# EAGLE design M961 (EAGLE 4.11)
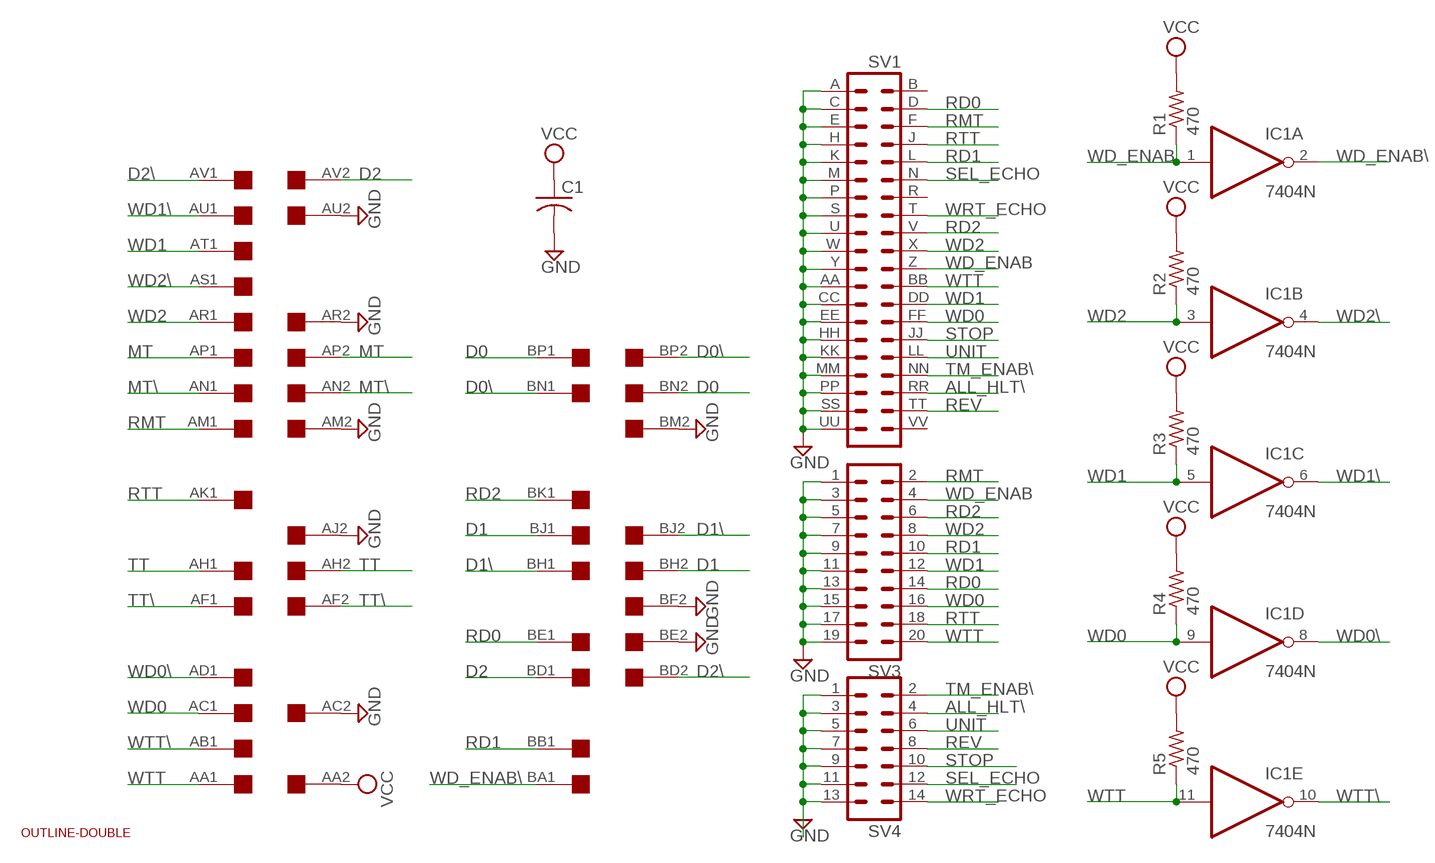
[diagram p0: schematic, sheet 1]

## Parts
C1  C-US050-025X075  [C050-025X075]
EDGE$1  DOUBLE  [EDGE-CON4]
IC1  7404N  [DIL14]
R1  470  R-US_0207/10  [0207/10]
R2  470  R-US_0207/10  [0207/10]
R3  470  R-US_0207/10  [0207/10]
R4  470  R-US_0207/10  [0207/10]
R5  470  R-US_0207/10  [0207/10]
SV1  DEC40PIN  [DEC40PIN]
SV3  MA10-2  [MA10-2]
SV4  MA07-2  [MA07-2]
U$2  OUTLINE-DOUBLE  [DOUBLE]

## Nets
ALL_HLT\: SV1.RR SV4.4
D0: EDGE$1.BN2 EDGE$1.BP1
D0\: EDGE$1.BN1 EDGE$1.BP2
D1: EDGE$1.BH2 EDGE$1.BJ1
D1\: EDGE$1.BH1 EDGE$1.BJ2
D2: EDGE$1.AV2 EDGE$1.BD1
D2\: EDGE$1.AV1 EDGE$1.BD2
GND: C1.2 EDGE$1.AC2 EDGE$1.AJ2 EDGE$1.AM2 EDGE$1.AR2 EDGE$1.AU2 EDGE$1.BE2 EDGE$1.BF2 EDGE$1.BM2 SV1.A SV1.AA SV1.C SV1.CC SV1.E SV1.EE SV1.H SV1.HH SV1.K SV1.KK SV1.M SV1.MM SV1.P SV1.PP SV1.S SV1.SS SV1.U SV1.UU SV1.W SV1.Y SV3.1 SV3.3 SV3.5 SV3.7 SV3.9 SV3.11 SV3.13 SV3.15 SV3.17 SV3.19 SV4.1 SV4.3 SV4.5 SV4.7 SV4.9 SV4.11 SV4.13
MT: EDGE$1.AP1 EDGE$1.AP2
MT\: EDGE$1.AN1 EDGE$1.AN2
RD0: EDGE$1.BE1 SV1.D SV3.14
RD1: EDGE$1.BB1 SV1.L SV3.10
RD2: EDGE$1.BK1 SV1.V SV3.6
REV: SV1.TT SV4.8
RMT: EDGE$1.AM1 SV1.F SV3.2
RTT: EDGE$1.AK1 SV1.J SV3.18
SEL_ECHO: SV1.N SV4.12
STOP: SV1.JJ SV4.10
TM_ENAB\: SV1.NN SV4.2
TT: EDGE$1.AH1 EDGE$1.AH2
TT\: EDGE$1.AF1 EDGE$1.AF2
UNIT: SV1.LL SV4.6
VCC: C1.1 EDGE$1.AA2 R1.2 R2.2 R3.2 R4.2 R5.2
WD0: EDGE$1.AC1 IC1.9(D:I) R4.1 SV1.FF SV3.16
WD0\: EDGE$1.AD1 IC1.8(D:O)
WD1: EDGE$1.AT1 IC1.5(C:I) R3.1 SV1.DD SV3.12
WD1\: EDGE$1.AU1 IC1.6(C:O)
WD2: EDGE$1.AR1 IC1.3(B:I) R2.1 SV1.X SV3.8
WD2\: EDGE$1.AS1 IC1.4(B:O)
WD_ENAB: IC1.1(A:I) R1.1 SV1.Z SV3.4
WD_ENAB\: EDGE$1.BA1 IC1.2(A:O)
WRT_ECHO: SV1.T SV4.14
WTT: EDGE$1.AA1 IC1.11(E:I) R5.1 SV1.BB SV3.20
WTT\: EDGE$1.AB1 IC1.10(E:O)
Unconnected: EDGE$1.AB2 EDGE$1.AD2 EDGE$1.AE1 EDGE$1.AE2 EDGE$1.AJ1 EDGE$1.AK2 EDGE$1.AL1 EDGE$1.AL2 EDGE$1.AS2 EDGE$1.AT2 EDGE$1.BA2 EDGE$1.BB2 EDGE$1.BC1 EDGE$1.BC2 EDGE$1.BF1 EDGE$1.BK2 EDGE$1.BL1 EDGE$1.BL2 EDGE$1.BM1 EDGE$1.BR1 EDGE$1.BR2 EDGE$1.BS1 EDGE$1.BS2 EDGE$1.BT1 EDGE$1.BT2 EDGE$1.BU1 EDGE$1.BU2 EDGE$1.BV1 EDGE$1.BV2 IC1.12(F:O) IC1.13(F:I) SV1.B SV1.R SV1.VV

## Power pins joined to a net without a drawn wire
GND: IC1.7(P:GND)
VCC: IC1.14(P:VCC)

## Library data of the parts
C1 = rcl:C-US: CAPACITOR, American symbol
EDGE$1 = dec-con:DOUBLE: Double-Height DEC board
IC1 = 74xx-us:74*04: Hex INVERTER
R1-R5 = rcl:R-US_: RESISTOR, American symbol
SV1 = dec-con:DEC40PIN: PIN HEADER
SV3 = con-lstb:MA10-2: PIN HEADER
SV4 = con-lstb:MA07-2: PIN HEADER
U$2 = dec-con:OUTLINE-*: Board outlines for DEC boards.

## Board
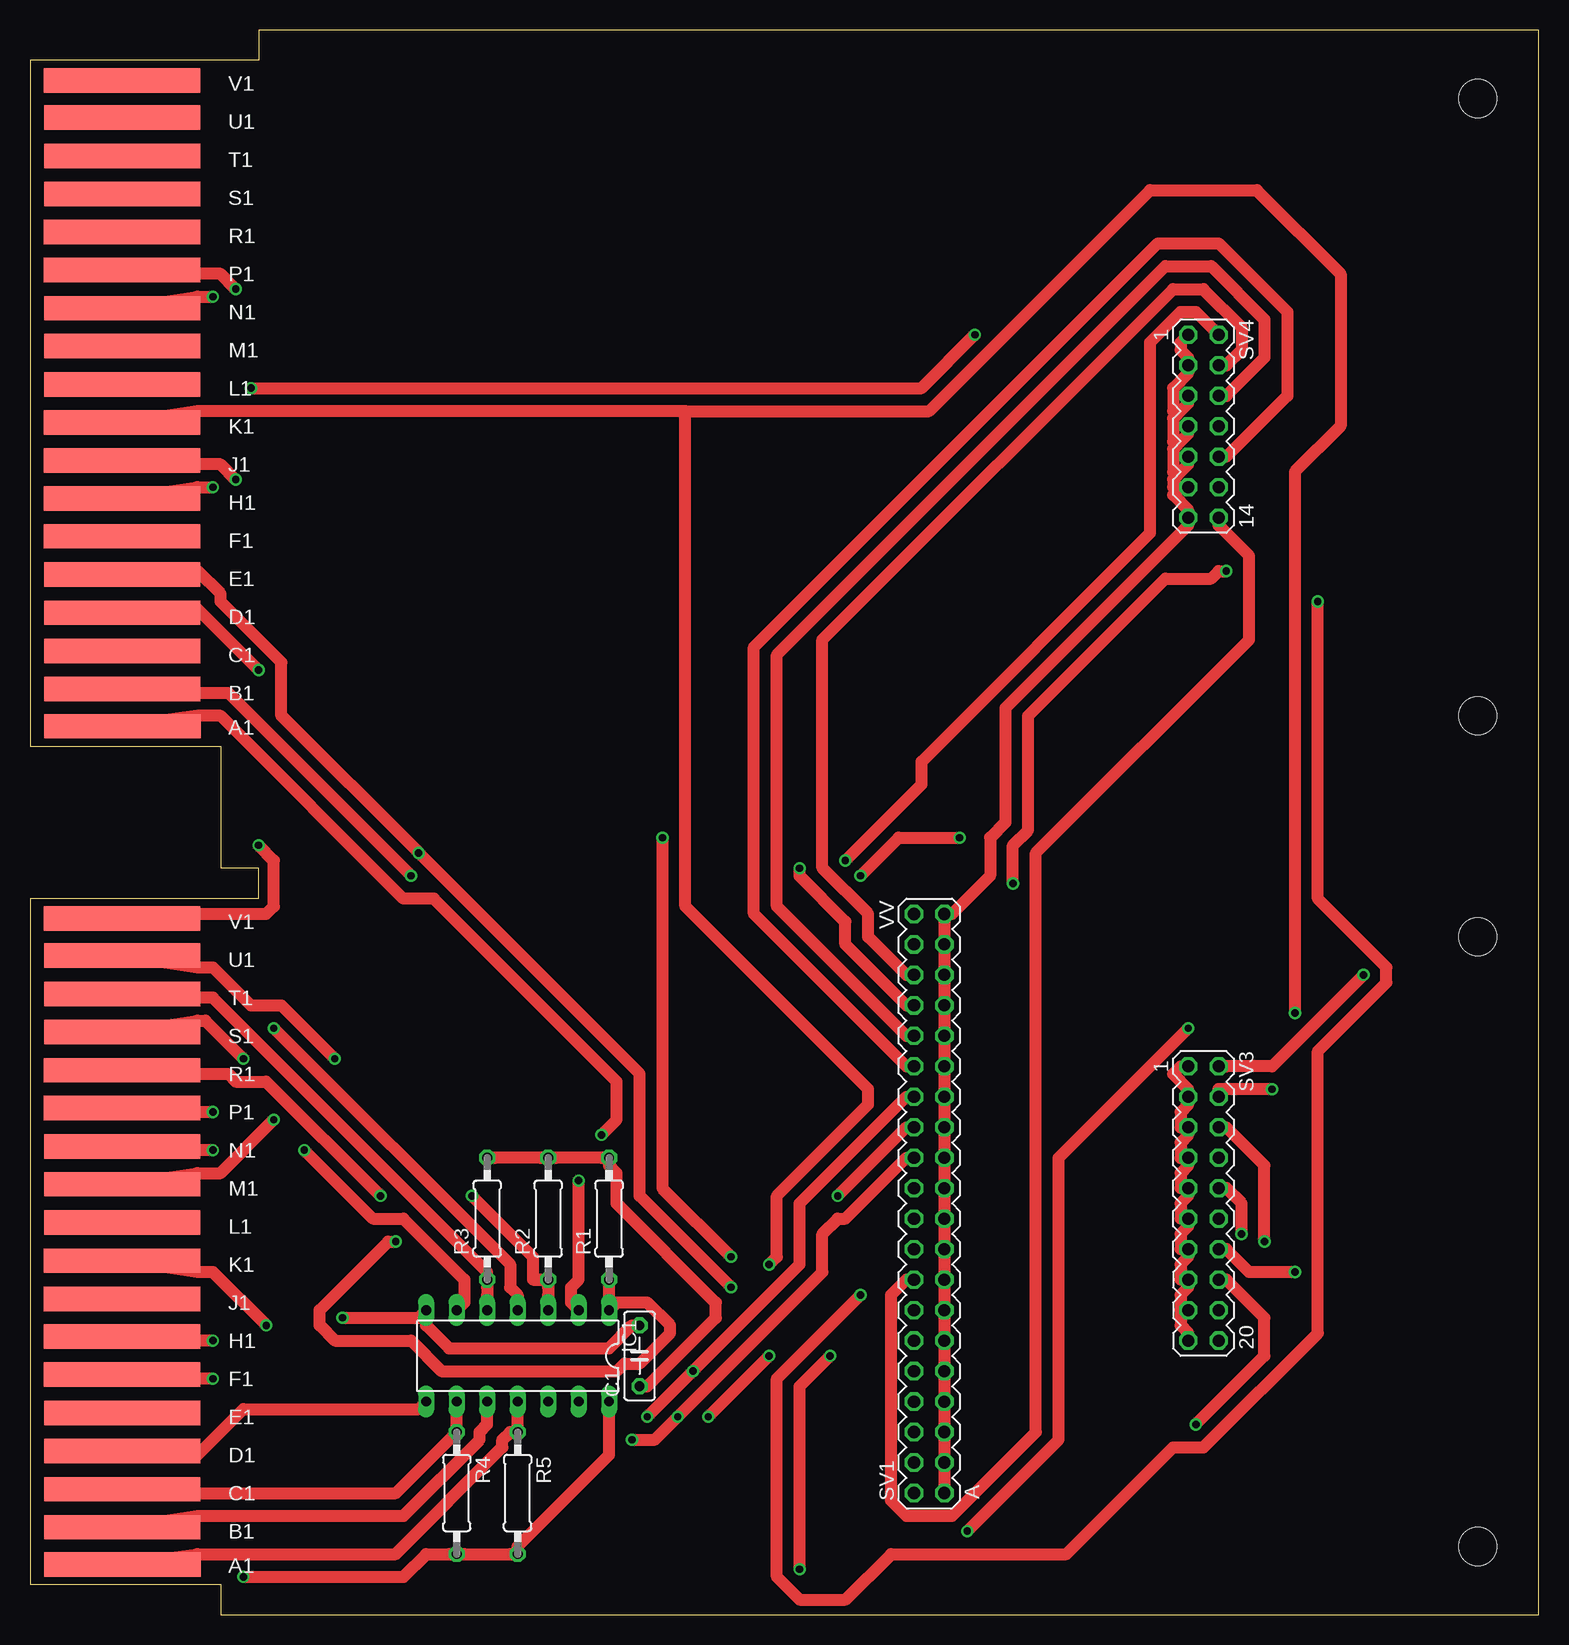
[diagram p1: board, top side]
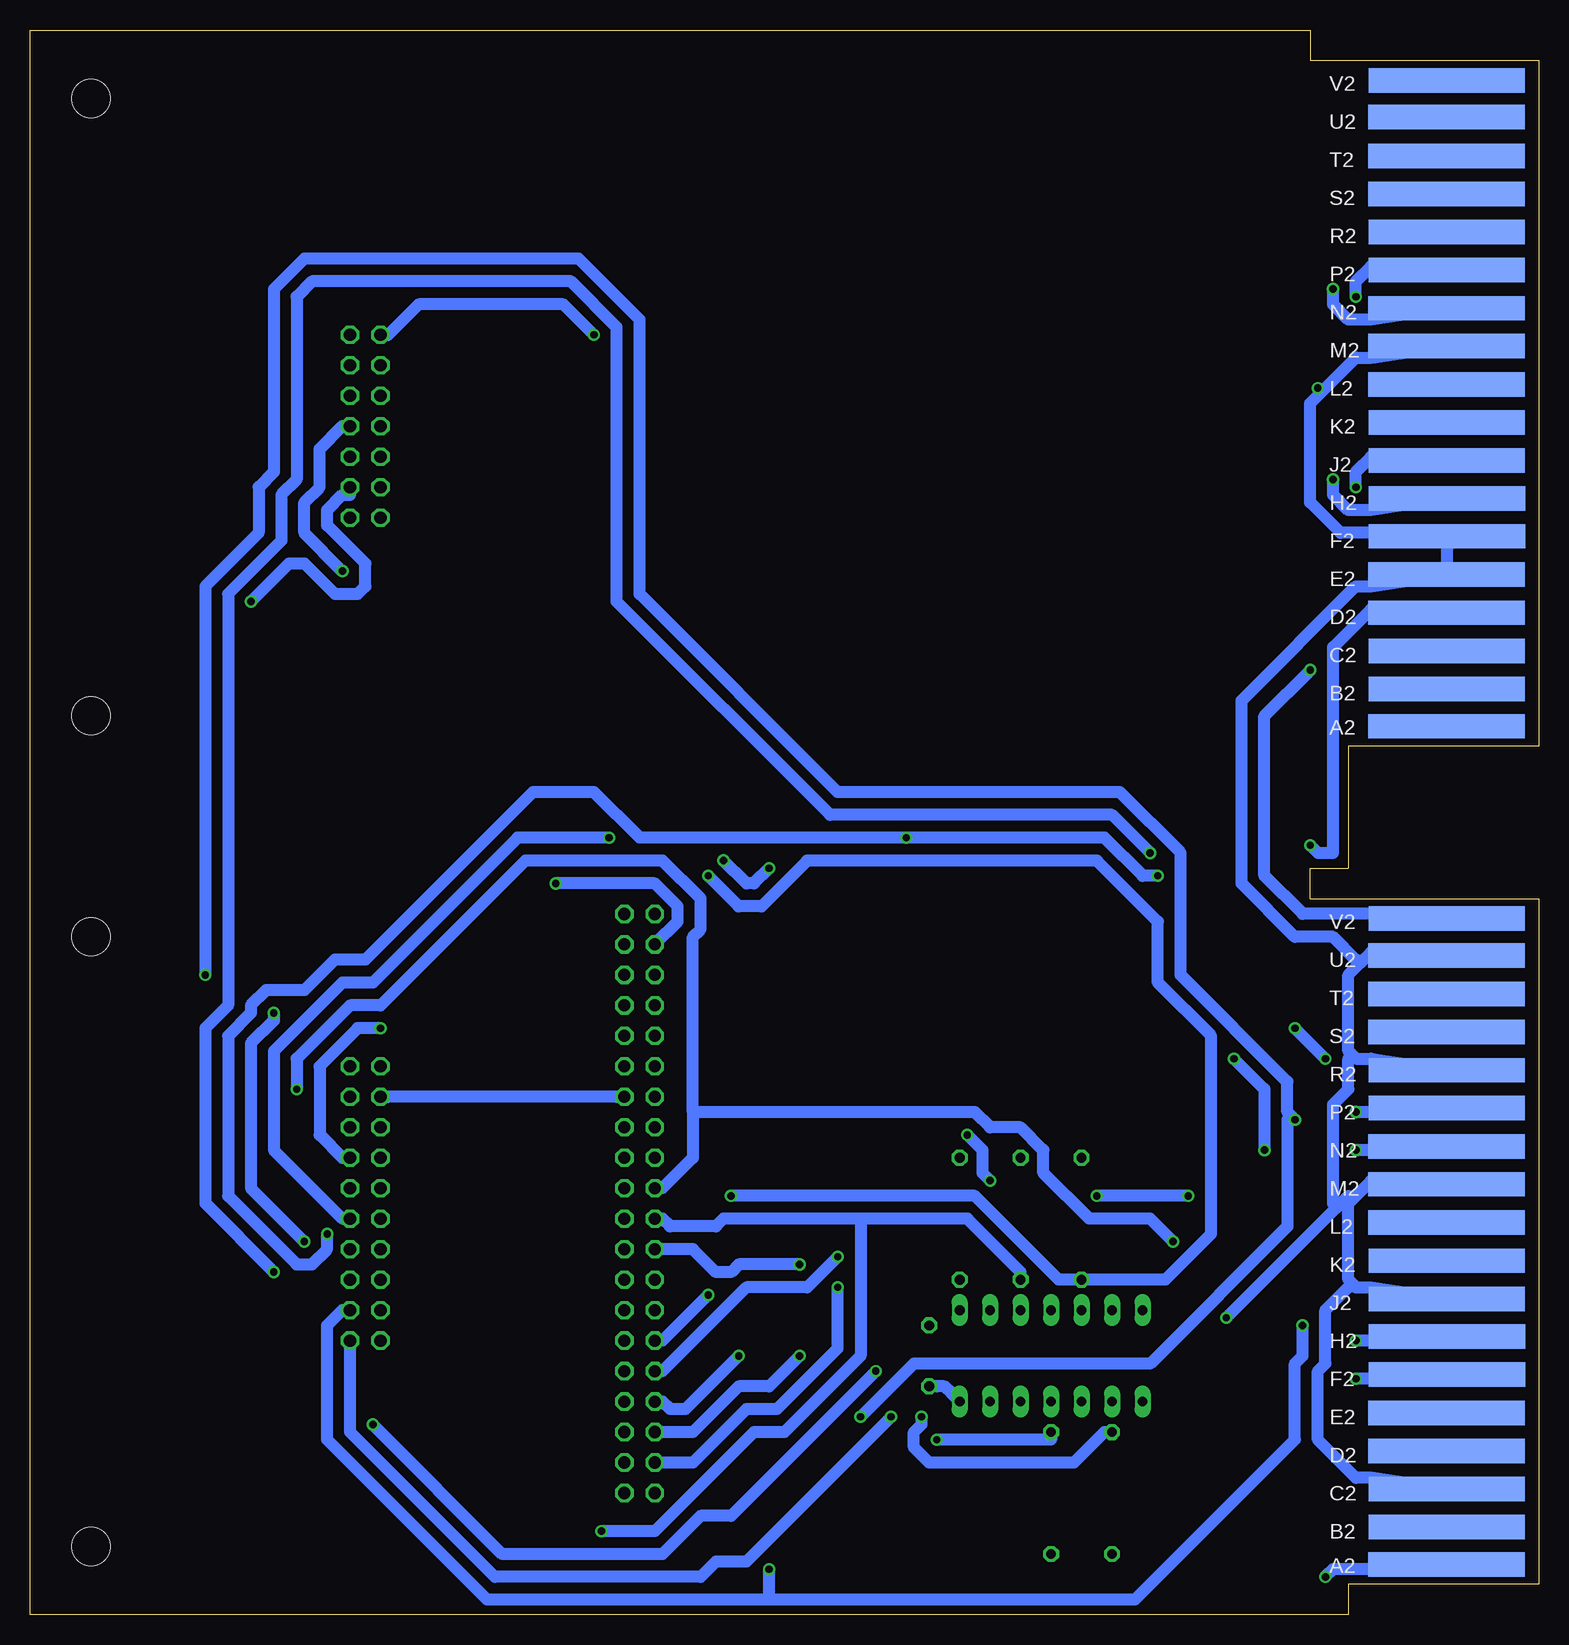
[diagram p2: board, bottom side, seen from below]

Size 125.73 x 132.08 mm. Coordinates in mm from the lower left corner, seen from the top.
Copper layers (1*16): Top 0.035mm / dielectric 1.5mm / Bottom 0.035mm
Design rules "40mils": minimum track width 40mil, minimum drill 24mil, track to track 20mil, track to pad 10mil, pad to pad 10mil, via to via 10mil, smd to smd 10mil, copper to edge 25mil, drill to drill 10mil, minimum pad ring 10mil, minimum via ring 8mil, stop-mask expansion 0mil, vias tented up to drill 0mil, thermal gap 10mil

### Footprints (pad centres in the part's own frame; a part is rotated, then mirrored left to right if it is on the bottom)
C050-025X075 = drill 0.813 octagon: 1 -2.54,0; 2 2.54,0
EDGE-CON4 = smd 13.017 x 2.032: AA1 7.709,4.207; AB1 7.684,7.312; AC1 7.684,10.474; AD1 7.684,13.665; AE1 7.693,16.84; AF1 7.668,20.041; AH1 7.668,23.19; AJ1 7.668,26.34; AK1 7.668,29.515; AL1 7.693,32.69; AM1 7.693,35.89; AN1 7.693,39.04; AP1 7.668,42.24; AR1 7.668,45.39; AS1 7.693,48.565; AT1 7.693,51.74; AU1 7.693,54.94; AV1 7.668,58.026; BA1 7.709,74.057; BB1 7.684,77.162; BC1 7.684,80.324; BD1 7.684,83.515; BE1 7.693,86.69; BF1 7.668,89.891; BH1 7.668,93.04; BJ1 7.668,96.19; BK1 7.668,99.365; BL1 7.693,102.54; BM1 7.693,105.74; BN1 7.693,108.89; BP1 7.668,112.09; BR1 7.668,115.24; BS1 7.693,118.415; BT1 7.693,121.59; BU1 7.693,124.79; BV1 7.668,127.876 | smd 13.017 x 2.032 bottom: AA2 7.69,4.207; AB2 7.668,7.328; AC2 7.668,10.49; AD2 7.693,13.665; AE2 7.693,16.84; AF2 7.642,20.041; AH2 7.642,23.19; AJ2 7.668,26.34; AK2 7.668,29.515; AL2 7.693,32.69; AM2 7.693,35.89; AN2 7.693,39.04; AP2 7.668,42.24; AR2 7.668,45.39; AS2 7.693,48.565; AT2 7.693,51.74; AU2 7.693,54.966; AV2 7.668,58.026; BA2 7.69,74.057; BB2 7.668,77.178; BC2 7.668,80.34; BD2 7.693,83.515; BE2 7.693,86.69; BF2 7.642,89.891; BH2 7.642,93.04; BJ2 7.668,96.19; BK2 7.668,99.365; BL2 7.693,102.54; BM2 7.693,105.74; BN2 7.693,108.89; BP2 7.668,112.09; BR2 7.668,115.24; BS2 7.693,118.415; BT2 7.693,121.59; BU2 7.693,124.816; BV2 7.668,127.876
DIL14 = drill 0.813 long: 1 -7.62,-3.81; 2 -5.08,-3.81; 3 -2.54,-3.81; 4 0,-3.81; 5 2.54,-3.81; 6 5.08,-3.81; 7 7.62,-3.81; 8 7.62,3.81; 9 5.08,3.81; 10 2.54,3.81; 11 0,3.81; 12 -2.54,3.81; 13 -5.08,3.81; 14 -7.62,3.81
0207/10 = drill 0.813 octagon: 1 -5.08,0; 2 5.08,0
DEC40PIN = drill 1.016 octagon: A -24.13,-1.27; AA 3.81,-1.27; B -24.13,1.27; BB 3.81,1.27; C -21.59,-1.27; CC 6.35,-1.27; D -21.59,1.27; DD 6.35,1.27; E -19.05,-1.27; EE 8.89,-1.27; F -19.05,1.27; FF 8.89,1.27; H -16.51,-1.27; HH 11.43,-1.27; J -16.51,1.27; JJ 11.43,1.27; K -13.97,-1.27; KK 13.97,-1.27; L -13.97,1.27; LL 13.97,1.27; M -11.43,-1.27; MM 16.51,-1.27; N -11.43,1.27; NN 16.51,1.27; P -8.89,-1.27; PP 19.05,-1.27; R -8.89,1.27; RR 19.05,1.27; S -6.35,-1.27; SS 21.59,-1.27; T -6.35,1.27; TT 21.59,1.27; U -3.81,-1.27; UU 24.13,-1.27; V -3.81,1.27; VV 24.13,1.27; W -1.27,-1.27; X -1.27,1.27; Y 1.27,-1.27; Z 1.27,1.27
MA10-2 = drill 1.016 octagon: 1 -11.43,-1.27; 2 -11.43,1.27; 3 -8.89,-1.27; 4 -8.89,1.27; 5 -6.35,-1.27; 6 -6.35,1.27; 7 -3.81,-1.27; 8 -3.81,1.27; 9 -1.27,-1.27; 10 -1.27,1.27; 11 1.27,-1.27; 12 1.27,1.27; 13 3.81,-1.27; 14 3.81,1.27; 15 6.35,-1.27; 16 6.35,1.27; 17 8.89,-1.27; 18 8.89,1.27; 19 11.43,-1.27; 20 11.43,1.27
MA07-2 = drill 1.016 octagon: 1 -7.62,-1.27; 2 -7.62,1.27; 3 -5.08,-1.27; 4 -5.08,1.27; 5 -2.54,-1.27; 6 -2.54,1.27; 7 0,-1.27; 8 0,1.27; 9 2.54,-1.27; 10 2.54,1.27; 11 5.08,-1.27; 12 5.08,1.27; 13 7.62,-1.27; 14 7.62,1.27
DOUBLE = hole 3.175: 120.65,56.515; 120.65,5.715; 120.65,74.93; 120.65,126.365

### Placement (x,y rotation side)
C1  50.8,21.59 90 top
EDGE$1  0,0 0 top
IC1  40.64,21.59 180 top
R1  48.26,33.02 90 top
R2  43.18,33.02 90 top
R3  38.1,33.02 90 top
R4  35.56,10.16 270 top
R5  40.64,10.16 270 top
SV1  74.93,34.29 90 top
SV3  97.79,34.29 270 top
SV4  97.79,99.06 270 top
U$2  0,0 0 top

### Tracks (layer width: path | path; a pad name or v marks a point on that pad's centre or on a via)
ALL_HLT\
  Top 1.016: SV1.RR 73.03,53.34 69.85,56.52 69.85,58.42 66.04,62.23 66.04,81.28 95.25,110.49 97.79,110.49 100.97,107.31 100.97,105.41 99.7,104.14 SV4.4
D0  (via drill 0.61)
  Top 1.016: v17.15,110.49 15.88,111.76 13.97,111.76 EDGE$1.BP1
  Bottom 1.016: v17.15,110.49 17.15,109.22 15.88,107.95 13.97,107.95 EDGE$1.BN2
D0\  (via drill 0.61)
  Top 1.016: v15.24,109.86 13.97,109.86 EDGE$1.BN1
  Bottom 1.016: v15.24,109.86 15.24,111.12 13.97,112.39 EDGE$1.BP2
D1  (via drill 0.61)
  Top 1.016: v17.15,94.61 15.88,95.89 13.97,95.89 EDGE$1.BJ1
  Bottom 1.016: v17.15,94.61 17.15,93.34 15.88,92.08 13.97,92.08 EDGE$1.BH2
D1\  (via drill 0.61)
  Top 1.016: v15.24,93.98 13.97,93.98 EDGE$1.BH1
  Bottom 1.016: v15.24,93.98 15.24,95.25 13.97,96.52 EDGE$1.BJ2
D2  (via drill 0.61)
  Top 1.016: v19.05,78.74 13.97,83.82 EDGE$1.BD1
  Bottom 1.016: v19.05,78.74 22.86,74.93 22.86,61.59 19.69,58.42 13.97,58.42 EDGE$1.AV2
D2\  (via drill 0.61)
  Top 1.016: v19.05,64.14 20.32,62.87 20.32,59.05 19.69,58.42 13.97,58.42 EDGE$1.AV1
  Bottom 1.016: v19.05,64.14 18.42,63.5 17.15,63.5 17.15,80.64 13.97,83.82 EDGE$1.BD2
GND  (via drill 0.61)
  Top 1.016: SV3.1 95.89,45.72 95.25,45.09 96.52,43.81 SV3.3 96.52,42.55 95.89,41.91 95.89,40.64 SV3.5 96.52,40.01 95.89,39.37 95.89,38.1 SV3.7 96.52,37.47 95.89,36.83 95.89,35.56 SV3.9 96.52,34.92 95.89,34.29 95.89,33.02 SV3.11 96.52,32.38 95.89,31.75 95.89,30.48 SV3.13 96.52,29.84 95.89,29.21 95.89,27.94 SV3.15 96.52,27.3 95.89,26.67 95.89,25.4 | 95.89,25.4 95.89,24.13 96.52,23.5 SV3.19 | 95.89,25.4 SV3.17 95.89,25.4 | SV4.1 95.89,106.05 95.89,105.41 96.52,104.78 SV4.3 96.52,103.5 95.25,102.23 95.25,100.33 95.57,100.01 | 95.57,93.66 95.89,93.98 SV4.11 | 95.57,93.66 95.25,93.34 96.52,92.08 SV4.13 96.52,90.81 81.28,75.56 81.28,66.04 80.01,64.77 80.01,61.59 76.84,58.42 SV1.UU 76.2,57.78 76.2,56.52 SV1.SS 76.2,55.24 76.2,53.98 SV1.PP 76.2,52.7 76.2,51.44 SV1.MM 76.2,50.16 76.2,48.9 SV1.KK 76.2,47.62 76.2,46.35 SV1.HH 76.2,45.09 76.2,43.81 SV1.EE 76.2,42.55 76.2,41.27 SV1.CC 76.2,40.01 76.2,38.73 SV1.AA 76.2,37.47 76.2,36.2 SV1.Y 76.2,34.92 76.2,33.66 SV1.W 76.2,32.38 76.2,31.11 SV1.U 76.2,29.84 76.2,28.57 SV1.S 76.2,27.3 76.2,26.04 SV1.P 76.2,24.77 76.2,23.5 SV1.M 76.2,22.23 76.2,20.95 SV1.K 76.2,19.68 76.2,18.41 SV1.H 76.2,17.14 76.2,15.88 SV1.E 76.2,14.61 76.2,13.34 SV1.C 76.2,12.06 76.2,10.79 SV1.A | 95.57,94.93 95.25,94.61 95.25,93.98 95.57,93.66 | 95.57,94.93 96.52,95.89 SV4.9 | 95.57,97.47 95.25,97.16 95.25,95.25 95.57,94.93 | 95.57,97.47 96.52,98.42 SV4.7 | 95.57,100.01 95.25,99.69 95.25,97.79 95.57,97.47 | 95.57,100.01 96.52,100.97 SV4.5 | C1.2 50.17,24.13 48.26,22.23 34.93,22.23 33.02,24.13 IC1.7 32.39,24.77 v26.04,24.77
  Top 1.016: v78.74,106.68 74.3,102.23 v18.42,102.23
  Bottom 1.016: SV3.3 95.89,43.18 76.84,43.18 SV1.EE | 18.1,101.92 19.05,100.97 19.05,92.71 16.51,90.17 13.97,90.17 EDGE$1.BF2 7.62,88.9 7.62,87.63 EDGE$1.BE2 13.97,85.72 15.24,85.72 24.77,76.2 24.77,60.96 20.32,56.52 17.15,56.52 15.24,54.61 14.92,54.29 | 18.1,101.92 15.24,104.78 13.97,104.78 EDGE$1.BM2 | 15.56,46.67 15.88,46.99 15.88,53.34 14.92,54.29 | 15.56,46.67 15.24,46.35 13.97,46.35 EDGE$1.AR2 | 14.92,54.29 13.97,55.24 EDGE$1.AU2 | 15.56,27.62 15.88,27.94 15.88,34.29 15.56,34.61 | 15.56,27.62 15.24,27.3 13.97,27.3 EDGE$1.AJ2 | 15.56,34.61 13.97,36.2 EDGE$1.AM2 | 16.83,33.97 15.88,34.92 15.56,34.61 | 16.83,33.97 v26.04,24.77 | EDGE$1.AC2 13.97,11.43 15.24,11.43 18.42,14.61 18.42,20.32 17.78,20.95 17.78,25.4 15.88,27.3 15.56,27.62 | 15.56,46.67 15.88,46.35 15.88,43.81 17.15,42.55 17.15,34.29 16.83,33.97 | v78.74,106.68 81.28,109.22 93.35,109.22 95.89,106.68 SV4.1 | 18.1,101.92 v18.42,102.23
MT  (via drill 0.61)
  Top 1.016: v15.24,41.91 13.97,41.91 EDGE$1.AP2
  Bottom 1.016: v15.24,41.91 13.97,41.91 EDGE$1.AP2
MT\  (via drill 0.61)
  Top 1.016: v15.24,38.73 13.97,38.73 EDGE$1.AN2
  Bottom 1.016: v15.24,38.73 13.97,38.73 EDGE$1.AN2
RD0  (via drill 0.61)
  Top 1.016: v58.42,27.3 50.8,34.92 50.8,45.09 v32.39,63.5 20.96,74.93 20.96,79.38 15.88,84.45 15.88,85.09 13.97,87 EDGE$1.BE1 | v105.41,28.57 101.6,28.57 99.7,30.48 SV3.14
  Bottom 1.016: v58.42,27.3 58.42,22.23 63.5,17.14 66.04,17.14 70.49,12.7 73.03,12.7 SV1.D | v105.41,28.57 111.13,34.29 111.13,48.9 109.22,50.8 109.22,85.09 104.78,89.53 104.78,93.34 103.51,94.61 103.51,109.86 102.24,111.12 80.65,111.12 76.84,107.31 76.84,84.45 59.06,66.67 35.56,66.67 v32.39,63.5
RD1  (via drill 0.61)
  Top 1.016: v31.75,61.59 16.51,76.83 13.97,76.83 EDGE$1.BB1 | v100.97,31.75 100.97,34.29 99.7,35.56 SV3.10 | v58.42,29.84 52.71,35.56 v52.71,64.77
  Bottom 1.016: v31.75,61.59 33.02,61.59 36.2,64.77 v52.71,64.77 74.93,64.77 78.74,68.58 83.82,68.58 97.79,54.61 100.33,54.61 102.87,52.07 106.05,52.07 107.32,50.8 107.32,50.16 109.22,48.26 109.22,34.92 103.51,29.21 102.24,29.21 100.97,30.48 v100.97,31.75 | v58.42,29.84 60.96,27.3 66.04,27.3 73.03,20.32 SV1.L
RD2  (via drill 0.61)
  Top 1.016: 54.61,100.33 74.93,100.33 93.35,118.75 102.24,118.75 109.22,111.76 109.22,99.06 105.41,95.25 v105.41,50.16 | 54.61,100.33 13.97,100.33 EDGE$1.BK1 | v102.87,31.11 102.87,37.47 99.7,40.64 SV3.6 | v61.6,29.21 62.23,29.84 62.23,34.92 69.85,42.55 69.85,43.81 54.61,59.05 54.61,100.33
  Bottom 1.016: v105.41,50.16 105.41,49.53 107.32,47.62 107.32,35.56 v102.87,31.11 | v61.6,29.21 66.68,29.21 67.31,28.57 68.58,28.57 70.49,30.48 73.03,30.48 SV1.V
REV  (via drill 0.61)
  Top 1.016: v99.7,87 99.06,87 98.43,86.36 94.62,86.36 83.19,74.93 83.19,65.41 81.92,64.14 v81.92,60.96
  Bottom 1.016: v99.7,87 102.87,90.17 102.87,92.71 101.6,93.98 101.6,97.16 99.7,99.06 SV4.8 | v81.92,60.96 73.66,60.96 71.76,59.05 71.76,57.78 SV1.TT
RMT  (via drill 0.61)
  Top 1.016: v20.32,41.27 15.88,36.83 13.97,36.83 EDGE$1.AM1 | v111.13,53.34 103.51,45.72 99.7,45.72 SV3.2 | v56.52,16.51 v61.6,21.59
  Bottom 1.016: 20.64,41.59 20.96,41.91 20.96,44.45 29.85,53.34 29.85,63.5 34.93,68.58 58.42,68.58 74.93,85.09 74.93,107.95 80.01,113.03 102.87,113.03 105.41,110.49 105.41,95.25 106.68,93.98 106.68,90.17 111.13,85.72 v111.13,53.34 | v20.32,41.27 20.64,41.59 | v61.6,21.59 64.14,19.05 66.68,19.05 70.49,15.24 73.03,15.24 SV1.F | v56.52,16.51 52.07,20.95 32.39,20.95 20.96,32.38 20.96,41.27 20.64,41.59
RTT  (via drill 0.61)
  Top 1.016: v19.69,24.13 15.24,28.57 13.97,28.57 EDGE$1.AK1 | v66.68,21.59 64.14,19.05 v64.14,3.81
  Bottom 1.016: v19.69,24.13 19.69,21.59 20.32,20.95 20.32,14.61 33.66,1.27 64.14,1.27 | 64.14,1.27 87.63,1.27 100.97,14.61 100.97,24.13 99.7,25.4 SV3.18 | v66.68,21.59 71.12,17.14 72.39,17.14 73.03,17.78 SV1.J | 64.14,1.27 v64.14,3.81
SEL_ECHO  (via drill 0.61)
  Top 1.016: v107.32,84.45 107.32,59.69 113.03,53.98 113.03,52.7 107.32,46.99 107.32,23.5 97.79,13.97 95.25,13.97 86.36,5.08 71.76,5.08 67.95,1.27 64.14,1.27 62.23,3.17 62.23,19.68 v69.22,26.67
  Bottom 1.016: v107.32,84.45 104.14,87.63 102.87,87.63 100.33,85.09 98.43,85.09 97.79,85.72 97.79,87.63 100.97,90.81 100.97,92.08 99.7,93.34 99.06,93.34 SV4.12 | v69.22,26.67 73.03,22.86 SV1.N
STOP
  Top 1.016: SV1.JJ 73.03,45.72 60.33,58.42 60.33,80.64 93.98,114.3 99.06,114.3 104.78,108.58 104.78,101.6 99.7,96.52 SV4.10
TM_ENAB\  (via drill 0.61)
  Top 1.016: v64.14,62.23 64.14,61.59 67.95,57.78 67.95,55.88 73.03,50.8 SV1.NN | v67.95,62.87 74.3,69.22 74.3,71.12 93.35,90.17 93.35,106.05 95.89,108.58 97.16,108.58 SV4.2
  Bottom 1.016: v64.14,62.23 65.41,60.96 66.04,60.96 v67.95,62.87
TT  (via drill 0.61)
  Top 1.016: v15.24,22.86 13.97,22.86 EDGE$1.AH1
  Bottom 1.016: v15.24,22.86 13.97,22.86 EDGE$1.AH2
TT\  (via drill 0.61)
  Top 1.016: v15.24,19.68 13.97,19.68 EDGE$1.AF1
  Bottom 1.016: v15.24,19.68 13.97,19.68 EDGE$1.AF2
UNIT
  Top 1.016: SV1.LL 73.03,48.26 62.23,59.05 62.23,80.01 94.62,112.39 98.43,112.39 102.87,107.95 102.87,104.78 99.7,101.6 SV4.6
VCC  (via drill 0.61)
  Top 1.016: R3.2 38.74,38.1 42.55,38.1 R2.2 43.82,38.1 47.63,38.1 R1.2 48.26,37.47 48.9,36.83 48.9,34.29 57.15,26.04 57.15,24.77 51.44,19.05 C1.1 | v17.78,3.17 31.12,3.17 33.02,5.08 34.93,5.08 R4.2 36.2,5.08 40.01,5.08 R5.2 40.64,5.71 48.26,13.34 48.26,16.51 IC1.14
  Bottom 1.016: IC1.14 48.9,18.41 49.53,19.05 50.17,19.05 C1.1 | v17.78,3.17 17.15,3.81 13.97,3.81 EDGE$1.AA2
WD0  (via drill 0.61)
  Top 1.016: EDGE$1.AC1 13.97,10.16 30.48,10.16 R4.1 35.56,15.88 35.56,16.51 IC1.9 | v51.44,16.51 v55.25,20.32 64.14,29.21 64.14,34.29 73.03,43.18 SV1.FF | v97.16,15.88 102.87,21.59 102.87,24.77 99.7,27.94 SV3.16
  Bottom 1.016: v51.44,16.51 51.44,15.88 52.07,15.24 52.07,13.97 50.8,12.7 38.74,12.7 36.2,15.24 R4.1 | v97.16,15.88 86.36,5.08 73.03,5.08 69.85,8.26 67.31,8.26 v55.25,20.32
WD0\
  Top 1.016: IC1.8 32.39,17.14 17.78,17.14 13.97,13.34 EDGE$1.AD1
WD1  (via drill 0.61)
  Top 1.016: EDGE$1.AT1 13.97,51.44 15.24,51.44 38.1,28.57 R3.1 38.1,27.3 38.1,26.67 IC1.5 | v67.31,34.92 73.03,40.64 SV1.DD | v77.47,64.77 72.39,64.77 v69.22,61.59
  Bottom 1.016: v67.31,34.92 46.99,34.92 40.01,27.94 38.74,27.94 R3.1 37.47,27.94 31.12,27.94 27.31,31.75 27.31,48.26 31.75,52.7 31.75,57.78 36.83,62.87 60.96,62.87 64.77,59.05 66.68,59.05 v69.22,61.59 | v77.47,64.77 85.09,64.77 97.16,52.7 99.7,52.7 105.41,46.99 105.41,38.73 99.7,33.02 SV3.12
WD1\  (via drill 0.61)
  Top 1.016: v25.4,46.35 20.96,50.8 18.42,50.8 15.24,53.98 13.97,53.98 EDGE$1.AU1 | v22.86,38.73 28.58,33.02 31.12,33.02 36.2,27.94 36.2,26.04 IC1.6
  Bottom 1.016: v25.4,46.35 22.86,43.81 v22.86,38.73
WD2  (via drill 0.61)
  Top 1.016: v29.21,34.92 19.69,44.45 17.15,44.45 16.51,45.09 13.97,45.09 EDGE$1.AR1 | v36.83,34.92 41.91,29.84 41.91,27.94 42.55,27.94 R2.1 43.18,27.3 43.18,26.67 IC1.3 | v96.52,48.9 85.73,38.1 85.73,14.61 v78.11,6.99
  Bottom 1.016: v29.21,34.92 v36.83,34.92 | 56.52,33.02 47.63,33.02 43.18,28.57 R2.1 | 56.52,33.02 67.95,33.02 68.58,32.38 72.39,32.38 73.03,33.02 SV1.X | v96.52,48.9 98.43,48.9 101.6,45.72 101.6,40.01 99.7,38.1 SV3.8 | v78.11,6.99 73.66,6.99 65.41,15.24 62.87,15.24 56.52,21.59 56.52,33.02
WD2\  (via drill 0.61)
  Top 1.016: v20.32,48.9 40.01,29.21 40.01,27.3 40.64,26.67 IC1.4 | v17.78,46.35 14.61,49.53 13.97,49.53 EDGE$1.AS1
  Bottom 1.016: v17.78,46.35 v20.32,48.9
WD_ENAB  (via drill 0.61)
  Top 1.016: R1.1 48.26,27.3 48.26,26.67 IC1.1 48.9,26.04 51.44,26.04 53.34,24.13 53.34,23.5 50.8,20.95 49.53,20.95 48.9,20.32 34.29,20.32 31.75,22.86 25.4,22.86 24.13,24.13 24.13,25.4 29.85,31.11 v30.48,31.11 | v103.51,43.81 99.06,43.81 SV3.4
  Bottom 1.016: 70.49,41.91 70.49,56.52 69.85,57.15 69.85,59.69 73.03,62.87 84.46,62.87 96.52,50.8 99.06,50.8 103.51,46.35 v103.51,43.81 | 70.49,41.91 70.49,38.1 73.03,35.56 SV1.Z | v30.48,31.11 32.39,33.02 37.47,33.02 41.28,36.83 41.28,38.73 43.18,40.64 45.72,40.64 46.99,41.91 70.49,41.91
WD_ENAB\  (via drill 0.61)
  Top 1.016: v47.63,40.01 48.9,41.27 48.9,44.45 33.66,59.69 31.12,59.69 15.88,74.93 13.97,74.93 EDGE$1.BA1 | v45.72,36.2 45.72,27.94 45.09,27.3 45.09,26.04 IC1.2
  Bottom 1.016: v47.63,40.01 46.36,38.73 46.36,36.83 v45.72,36.2
WRT_ECHO
  Top 1.016: SV1.T 73.03,27.94 71.76,26.67 71.76,9.53 73.03,8.26 76.84,8.26 83.82,15.24 83.82,63.5 101.6,81.28 101.6,88.27 99.06,90.81 SV4.14
WTT  (via drill 0.61)
  Top 1.016: EDGE$1.AA1 13.97,5.08 30.48,5.08 39.37,13.97 39.37,14.61 40.01,15.24 R5.1 40.64,15.88 40.64,16.51 IC1.11 | v50.17,14.61 52.07,14.61 v53.98,16.51 66.04,28.57 66.04,31.75 67.31,33.02 67.95,33.02 73.03,38.1 SV1.BB
  Bottom 1.016: v50.17,14.61 40.64,14.61 R5.1 | v53.98,16.51 66.04,4.45 68.58,4.45 69.85,3.17 87,3.17 99.06,15.24 99.06,22.23 SV3.20
WTT\
  Top 1.016: IC1.10 38.1,16.51 38.1,15.88 37.47,15.24 37.47,14.61 31.12,8.26 13.97,8.26 EDGE$1.AB1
